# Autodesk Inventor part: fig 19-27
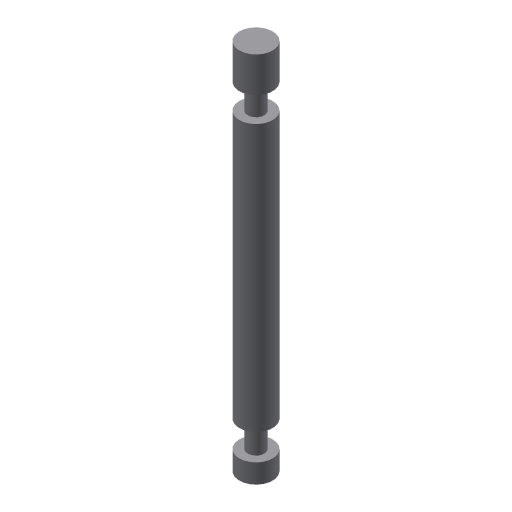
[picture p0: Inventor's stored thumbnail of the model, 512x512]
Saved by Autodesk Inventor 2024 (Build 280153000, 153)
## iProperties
Created: 2013-07
Part Number: fig 19-27
Material: Generic
Document SubType Name: Modeling
Designer: CADCIM
Density: 1 g/cm^3
Appearance: Default
Author: CADCIM
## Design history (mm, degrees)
sketch "Sketch3"
  geometry: L1 (0, 19.325)-(1.664, 19.325); L2 (1.664, 19.325)-(1.664, 15.806); L3 (1.664, 15.806)-(0.832, 15.806); L4 (0.832, 15.806)-(0.832, 13.31); L5 (0.832, 13.31)-(1.664, 13.31); L6 (1.664, 13.31)-(1.664, -13.31); L7 (1.664, -13.31)-(0.832, -13.31); L8 (0.832, -13.31)-(0.832, -15.934); L9 (0.832, -15.934)-(1.664, -15.934); L10 (1.664, -15.934)-(1.664, -17.853); L11 (1.664, -17.853)-(0, -17.853); L12 (0, -17.853)-(0, 19.325); 1 further point
  constraints: 24 end point, 8 perpendicular, 6 point on line, 1 horizontal
revolve "Revolution1" sketch "Sketch3" stored, may be unused: angle "d8" = 90 deg
body "Solid2"
